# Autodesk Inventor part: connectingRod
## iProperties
Created: 2009-04
Part Number: connectingRod
Document SubType Name: Modeling
Designer: Lochan
Density: 1 g/cm^3
Author: Lochan
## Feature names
1. Extrusion1
2. Revolution1
3. Mirror1
